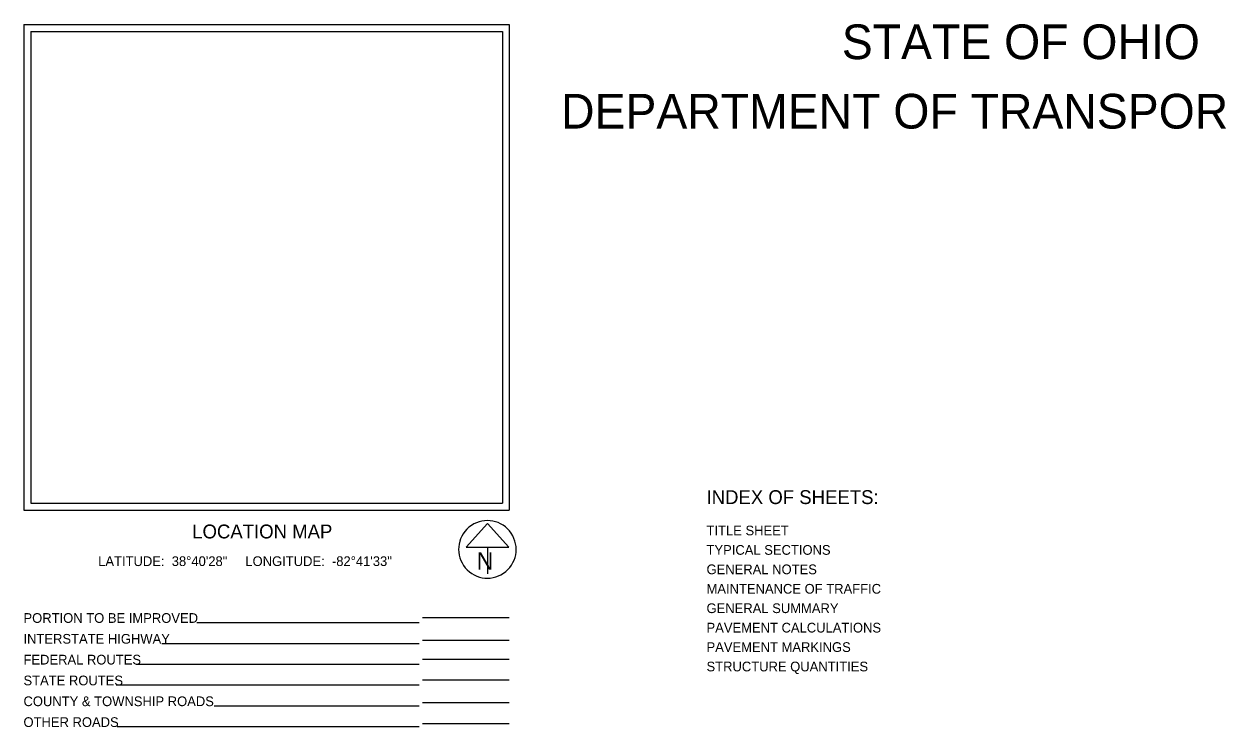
# Model space of a CAD drawing. Extents: x 0 to 82.7, y -0.2 to 22.
# Drawn here: x 53.16 to 70.38, y 10.17 to 20.3 of the extents above; entities that cross this region are included whole.
import ezdxf

# ---------------------------------------------------------------- set-up
doc = ezdxf.new("R2010")
doc.units = 0
doc.layers.add('SH_Data', color=7, linetype='Continuous')
doc.layers.add('SH_Text', color=7, linetype='Continuous')

msp = doc.modelspace()

# ---------------------------------------------------------------- linework, layer by layer
at = {"layer": 'SH_Data'}
for p, q in [((53.16, 20.296), (60.16, 20.296)), ((53.16, 20.296), (53.16, 13.296)), ((53.26, 20.196), (53.26, 13.396)), ((53.26, 20.196), (60.06, 20.196)), ((60.06, 20.196), (60.06, 13.396)), ((60.16, 20.296), (60.16, 13.296)), ((53.16, 13.296), (60.16, 13.296)), ((53.26, 13.396), (60.06, 13.396)), ((53.26, 13.396), (53.26, 13.396)), ((59.844, 13.106), (59.537, 12.764)), ((60.152, 12.764), (59.844, 13.106)), ((59.537, 12.764), (60.152, 12.764)), ((59.844, 12.764), (59.844, 12.378)), ((59.844, 12.732), (59.844, 12.732)), ((59.844, 12.732), (59.844, 12.732)), ((58.91, 11.752), (60.16, 11.752)), ((58.86, 11.673), (55.653, 11.673)), ((58.86, 11.373), (55.149, 11.373)), ((60.16, 11.417), (58.91, 11.417)), ((58.86, 11.073), (54.779, 11.073)), ((60.16, 11.146), (58.91, 11.146)), ((58.86, 10.773), (54.489, 10.773)), ((60.16, 10.846), (58.91, 10.846)), ((60.16, 10.519), (58.91, 10.519)), ((58.86, 10.473), (55.905, 10.473)), ((58.86, 10.173), (54.507, 10.173)), ((60.16, 10.219), (58.91, 10.219))]:
    msp.add_line(p, q, dxfattribs=at)
msp.add_arc((59.844, 12.732), 0.415, 129.7798, 129.7633, dxfattribs=at)

# ---------------------------------------------------------------- texts
msp.add_text('N', height=0.25, dxfattribs=at).set_placement((59.689, 12.44))
at = {"layer": 'SH_Text'}
for s, height, p in [('STATE OF OHIO', 0.5, (64.955, 19.796)), ('DEPARTMENT OF TRANSPORTATION', 0.5, (60.906, 18.796)), ('INDEX OF SHEETS:', 0.2, (63.004, 13.385)), ('LOCATION MAP', 0.2, (55.587, 12.89)), ('TITLE SHEET', 0.14, (63.004, 12.934)), ('TYPICAL SECTIONS', 0.14, (63.004, 12.654)), ('LATITUDE:  38°40\'28"     LONGITUDE:  -82°41\'33"', 0.14, (54.231, 12.492)), ('GENERAL NOTES', 0.14, (63.004, 12.374)), ('MAINTENANCE OF TRAFFIC', 0.14, (63.004, 12.094)), ('GENERAL SUMMARY', 0.14, (63.004, 11.814)), ('PORTION TO BE IMPROVED', 0.14, (53.154, 11.673)), ('PAVEMENT CALCULATIONS', 0.14, (63.004, 11.534)), ('INTERSTATE HIGHWAY', 0.14, (53.154, 11.373)), ('PAVEMENT MARKINGS', 0.14, (63.004, 11.254)), ('FEDERAL ROUTES', 0.14, (53.154, 11.073)), ('STRUCTURE QUANTITIES', 0.14, (63.004, 10.974)), ('STATE ROUTES', 0.14, (53.154, 10.773)), ('COUNTY & TOWNSHIP ROADS', 0.14, (53.154, 10.473)), ('OTHER ROADS', 0.14, (53.154, 10.173))]:
    msp.add_text(s, height=height, dxfattribs=at).set_placement(p)

doc.saveas('drawing.dxf')
